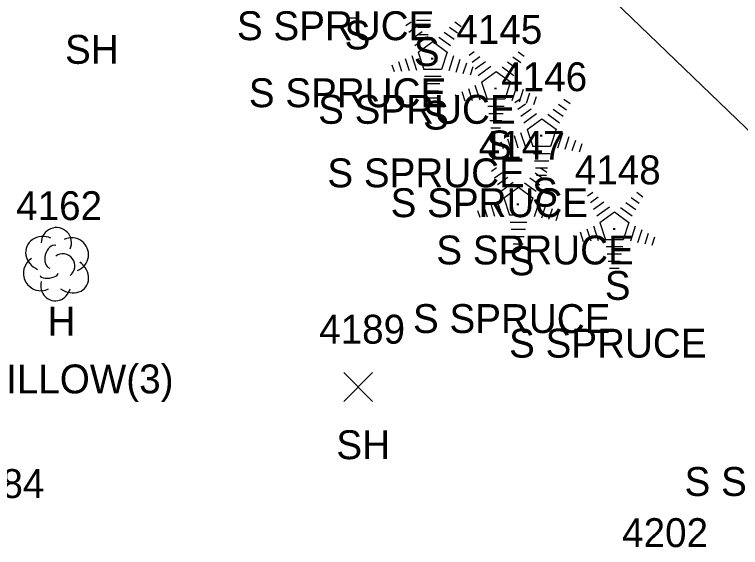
# Model space of a CAD drawing. Extents: x 1482574 to 1485769, y 580696 to 595649.
# Drawn here: x 1483651.3 to 1483701.6, y 583369.1 to 583406 of the extents above; entities that cross this region are included whole.
import ezdxf

# ---------------------------------------------------------------- set-up
doc = ezdxf.new("R2010")
doc.units = 0
for name, color, linetype in [('L_A', 7, 'Continuous'), ('L_C', 7, 'Continuous'), ('L_I', 7, 'Continuous'), ('L_TIC', 7, 'Continuous'), ('LELB', 7, 'Continuous'), ('LTC', 7, 'Continuous'), ('LTD', 7, 'Continuous')]:
    doc.layers.add(name, color=color, linetype=linetype)

msp = doc.modelspace()

# ---------------------------------------------------------------- linework, layer by layer
at = {"layer": 'L_TIC'}
for points in [[(1483674.12, 583379.228), (1483676.12, 583381.228)], [(1483676.12, 583379.228), (1483674.12, 583381.228)]]:
    msp.add_lwpolyline(points, dxfattribs=at)
at = {"layer": 'LELB'}
msp.add_lwpolyline([(1483727.449, 583370.792), (1483706.196, 583394.109), (1483684.342, 583415.146), (1483662.731, 583438.521), (1483641.557, 583461.504), (1483625.996, 583477.101)], dxfattribs=at)
at = {"layer": 'LTC'}
for p, q in [((1483675.168, 583405.767), (1483674.493, 583405.767)), ((1483680.136, 583405.618), (1483679.148, 583405.618)), ((1483678.426, 583405.264), (1483678.781, 583405.522)), ((1483678.636, 583404.799), (1483679.165, 583405.183)), ((1483680.052, 583405.118), (1483679.221, 583405.118)), ((1483681.453, 583405.156), (1483682.003, 583404.757)), ((1483681.824, 583405.505), (1483682.244, 583405.2)), ((1483678.845, 583404.333), (1483679.549, 583404.844)), ((1483679.968, 583404.618), (1483679.293, 583404.618)), ((1483681.082, 583404.808), (1483681.762, 583404.314)), ((1483679.055, 583403.867), (1483679.933, 583404.505)), ((1483679.28, 583403.412), (1483680.291, 583404.147)), ((1483680.291, 583404.147), (1483681.288, 583403.422)), ((1483680.711, 583404.46), (1483681.521, 583403.871)), ((1483678.825, 583403.193), (1483679.156, 583402.174)), ((1483679.28, 583403.412), (1483679.667, 583402.219)), ((1483681.288, 583403.422), (1483680.897, 583402.219)), ((1483681.726, 583403.151), (1483681.388, 583402.111)), ((1483682.806, 583403.197), (1483683.161, 583403.455)), ((1483683.016, 583402.732), (1483683.545, 583403.116)), ((1483685.833, 583403.089), (1483686.383, 583402.69)), ((1483686.204, 583403.438), (1483686.624, 583403.133)), ((1483677.914, 583402.76), (1483678.126, 583402.108)), ((1483678.37, 583402.977), (1483678.641, 583402.141)), ((1483682.17, 583402.9), (1483681.883, 583402.016)), ((1483682.615, 583402.65), (1483682.378, 583401.921)), ((1483683.225, 583402.266), (1483683.929, 583402.777)), ((1483685.462, 583402.741), (1483686.142, 583402.247)), ((1483677.459, 583402.543), (1483677.611, 583402.075)), ((1483680.897, 583402.219), (1483679.667, 583402.219)), ((1483683.059, 583402.4), (1483682.872, 583401.826)), ((1483683.435, 583401.8), (1483684.313, 583402.438)), ((1483683.66, 583401.345), (1483684.671, 583402.08)), ((1483684.671, 583402.08), (1483685.668, 583401.355)), ((1483685.091, 583402.393), (1483685.901, 583401.804)), ((1483680.859, 583401.719), (1483679.714, 583401.719)), ((1483680.775, 583401.219), (1483679.787, 583401.219)), ((1483683.205, 583401.126), (1483683.536, 583400.107)), ((1483683.66, 583401.345), (1483684.047, 583400.152)), ((1483685.668, 583401.355), (1483685.277, 583400.152)), ((1483686.106, 583401.084), (1483685.768, 583400.044)), ((1483680.691, 583400.719), (1483679.86, 583400.719)), ((1483682.294, 583400.693), (1483682.506, 583400.041)), ((1483682.75, 583400.91), (1483683.021, 583400.074)), ((1483686.55, 583400.833), (1483686.263, 583399.949)), ((1483686.995, 583400.583), (1483686.758, 583399.854)), ((1483680.607, 583400.219), (1483679.932, 583400.219)), ((1483681.839, 583400.476), (1483681.991, 583400.008)), ((1483685.277, 583400.152), (1483684.047, 583400.152)), ((1483685.972, 583399.922), (1483686.327, 583400.18)), ((1483687.439, 583400.333), (1483687.252, 583399.759)), ((1483689.37, 583400.163), (1483689.79, 583399.858)), ((1483685.239, 583399.652), (1483684.094, 583399.652)), ((1483686.182, 583399.457), (1483686.711, 583399.841)), ((1483688.999, 583399.814), (1483689.549, 583399.415)), ((1483685.155, 583399.152), (1483684.167, 583399.152)), ((1483686.391, 583398.991), (1483687.095, 583399.502)), ((1483686.601, 583398.525), (1483687.479, 583399.163)), ((1483688.257, 583399.118), (1483689.067, 583398.529)), ((1483688.628, 583399.466), (1483689.308, 583398.972)), ((1483685.071, 583398.652), (1483684.24, 583398.652)), ((1483686.826, 583398.07), (1483687.837, 583398.805)), ((1483687.837, 583398.805), (1483688.834, 583398.08)), ((1483684.987, 583398.152), (1483684.312, 583398.152)), ((1483686.826, 583398.07), (1483687.213, 583396.877)), ((1483688.834, 583398.08), (1483688.443, 583396.877)), ((1483685.916, 583397.635), (1483686.187, 583396.799)), ((1483686.371, 583397.851), (1483686.702, 583396.832)), ((1483689.272, 583397.809), (1483688.934, 583396.769)), ((1483689.716, 583397.558), (1483689.429, 583396.674)), ((1483685.005, 583397.201), (1483685.157, 583396.733)), ((1483685.46, 583397.418), (1483685.672, 583396.766)), ((1483690.161, 583397.308), (1483689.924, 583396.579)), ((1483690.605, 583397.058), (1483690.418, 583396.484)), ((1483688.443, 583396.877), (1483687.213, 583396.877)), ((1483688.405, 583396.377), (1483687.26, 583396.377)), ((1483688.321, 583395.877), (1483687.333, 583395.877)), ((1483684.355, 583395.172), (1483684.71, 583395.43)), ((1483684.565, 583394.707), (1483685.094, 583395.091)), ((1483687.382, 583395.064), (1483687.932, 583394.665)), ((1483688.237, 583395.377), (1483687.406, 583395.377)), ((1483687.753, 583395.413), (1483688.173, 583395.108)), ((1483684.774, 583394.241), (1483685.478, 583394.752)), ((1483687.011, 583394.716), (1483687.691, 583394.222)), ((1483688.153, 583394.877), (1483687.478, 583394.877)), ((1483684.984, 583393.775), (1483685.862, 583394.413)), ((1483685.209, 583393.32), (1483686.22, 583394.055)), ((1483686.22, 583394.055), (1483687.217, 583393.33)), ((1483686.64, 583394.368), (1483687.45, 583393.779)), ((1483691.008, 583393.469), (1483691.363, 583393.727)), ((1483694.406, 583393.71), (1483694.826, 583393.405)), ((1483684.754, 583393.101), (1483685.085, 583392.082)), ((1483685.209, 583393.32), (1483685.596, 583392.127)), ((1483687.217, 583393.33), (1483686.826, 583392.127)), ((1483687.655, 583393.059), (1483687.317, 583392.019)), ((1483691.218, 583393.004), (1483691.747, 583393.388)), ((1483691.427, 583392.538), (1483692.131, 583393.049)), ((1483693.664, 583393.013), (1483694.344, 583392.519)), ((1483694.035, 583393.361), (1483694.585, 583392.962)), ((1483683.843, 583392.668), (1483684.055, 583392.016)), ((1483684.299, 583392.885), (1483684.57, 583392.049)), ((1483688.099, 583392.808), (1483687.812, 583391.924)), ((1483688.544, 583392.558), (1483688.307, 583391.829)), ((1483691.637, 583392.072), (1483692.515, 583392.71)), ((1483693.293, 583392.665), (1483694.103, 583392.076)), ((1483683.388, 583392.451), (1483683.54, 583391.983)), ((1483686.826, 583392.127), (1483685.596, 583392.127)), ((1483688.988, 583392.308), (1483688.801, 583391.734)), ((1483691.862, 583391.617), (1483692.873, 583392.352)), ((1483692.873, 583392.352), (1483693.87, 583391.627)), ((1483686.788, 583391.627), (1483685.643, 583391.627)), ((1483691.862, 583391.617), (1483692.249, 583390.424)), ((1483693.87, 583391.627), (1483693.479, 583390.424)), ((1483686.704, 583391.127), (1483685.716, 583391.127)), ((1483690.952, 583391.182), (1483691.223, 583390.346)), ((1483691.407, 583391.398), (1483691.738, 583390.379)), ((1483694.308, 583391.356), (1483693.97, 583390.316)), ((1483694.752, 583391.105), (1483694.465, 583390.221)), ((1483686.62, 583390.627), (1483685.789, 583390.627)), ((1483690.041, 583390.748), (1483690.193, 583390.28)), ((1483690.496, 583390.965), (1483690.708, 583390.313)), ((1483695.197, 583390.855), (1483694.96, 583390.126)), ((1483695.641, 583390.605), (1483695.454, 583390.031)), ((1483686.536, 583390.127), (1483685.861, 583390.127)), ((1483693.479, 583390.424), (1483692.249, 583390.424)), ((1483693.441, 583389.924), (1483692.296, 583389.924)), ((1483693.357, 583389.424), (1483692.369, 583389.424)), ((1483693.273, 583388.924), (1483692.442, 583388.924)), ((1483693.189, 583388.424), (1483692.514, 583388.424))]:
    msp.add_line(p, q, dxfattribs=at)
at = {"layer": 'LTD'}
msp.add_line((1483654.175, 583388.784), (1483654.175, 583388.784), dxfattribs=at)
msp.add_line((1483654.175, 583388.784), (1483654.175, 583388.784), dxfattribs=at)
msp.add_arc((1483654.222, 583390.218), 1.047, 335.5272, 180.9563, dxfattribs=at)
for centre, major_axis, ratio, start_param, end_param in [((1483653.383, 583389.451), (1.21, -0.512), 0.895232, 1.570796, 4.712389), ((1483655.217, 583389.368), (-1.141, -0.483), 0.949671, 1.570796, 4.712389), ((1483653.967, 583389.242), (-0.208, -0.792), 0.645439, 3.141593, 6.283185), ((1483654.675, 583388.617), (-0.5, 0.667), 0.989748, 3.141593, 6.283185), ((1483653.092, 583388.075), (0.584, -1.042), 0.959034, 3.141593, 6.283185), ((1483655.175, 583387.951), (-1.09, 0.792), 0.841452, 1.570796, 4.712389), ((1483653.717, 583388.034), (-0.625, -0.083), 0.423636, 0, 3.141593), ((1483654.175, 583387.284), (0.265, 1.061), 0.942809, 1.570796, 4.712389)]:
    msp.add_ellipse(centre, major_axis=major_axis, ratio=ratio, start_param=start_param, end_param=end_param, dxfattribs=at)

# ---------------------------------------------------------------- texts
at = {"layer": 'L_A'}
for s, p in [('S', (1483674.178, 583403.604)), ('SH', (1483654.822, 583402.609)), ('S', (1483678.978, 583402.455)), ('S', (1483679.617, 583398.056)), ('S', (1483683.997, 583395.989)), ('S', (1483687.163, 583392.714)), ('S', (1483685.546, 583387.964)), ('S', (1483692.199, 583386.261)), ('H', (1483653.608, 583383.784)), ('SH', (1483673.608, 583375.228))]:
    msp.add_text(s, height=2, dxfattribs=at).set_placement(p)
at = {"layer": 'L_C'}
for s, p in [('S SPRUCE', (1483666.724, 583404.246)), ('S SPRUCE', (1483667.548, 583399.604)), ('S SPRUCE', (1483672.348, 583398.455)), ('S SPRUCE', (1483672.987, 583394.056)), ('S SPRUCE', (1483677.367, 583391.989)), ('S SPRUCE', (1483680.533, 583388.714)), ('S SPRUCE', (1483678.916, 583383.964)), ('S SPRUCE', (1483685.569, 583382.261)), ('M WILLOW(3)', (1483645.246, 583379.784)), ('S SPRUCE', (1483697.722, 583372.681))]:
    msp.add_text(s, height=2, dxfattribs=at).set_placement(p)
at = {"layer": 'L_I'}
for s, p in [('4145', (1483681.918, 583403.989)), ('4146', (1483685.029, 583400.714)), ('4147', (1483683.467, 583395.964)), ('4148', (1483690.12, 583394.261)), ('4162', (1483651.435, 583391.784)), ('4189', (1483672.419, 583383.228)), ('4184', (1483647.44, 583372.539)), ('4202', (1483693.398, 583369.14))]:
    msp.add_text(s, height=2, dxfattribs=at).set_placement(p)
at = {"layer": 'LTC'}
for p in [(1483680.174, 583403.16), (1483684.554, 583401.093), (1483687.72, 583397.818), (1483686.103, 583393.068), (1483692.756, 583391.365)]:
    msp.add_text('.', height=1.037, rotation=270, dxfattribs=at).set_placement(p)

doc.saveas('drawing.dxf')
